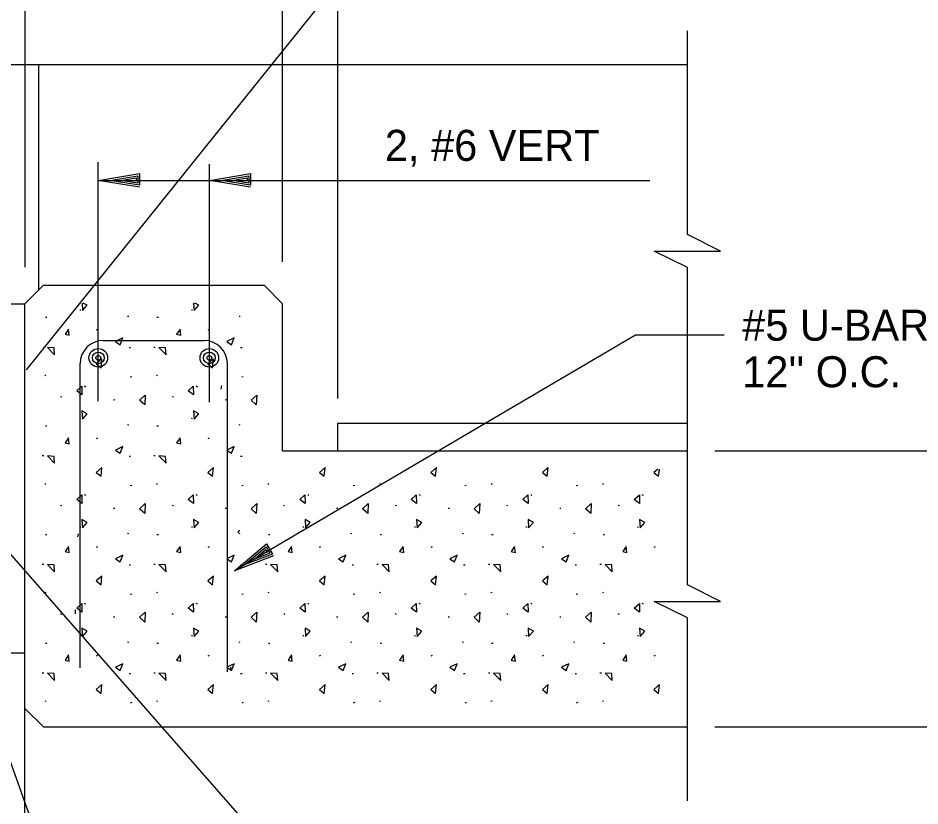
# Model space of a CAD drawing. Extents: x 22369.6 to 22428.3, y 22369.6 to 22415.
# Drawn here: x 22417.44 to 22422.89, y 22389.3 to 22394.06 of the extents above; entities that cross this region are included whole.
import ezdxf

# ---------------------------------------------------------------- set-up
doc = ezdxf.new("R2010")
doc.units = 0
for name, color, linetype in [('Level 1', 7, 'Continuous'), ('Level 10', 7, 'Continuous'), ('Level 2', 7, 'Continuous'), ('Level 4', 7, 'Continuous'), ('Level 7', 7, 'Continuous'), ('Level 8', 7, 'Continuous')]:
    doc.layers.add(name, color=color, linetype=linetype)

msp = doc.modelspace()

# ---------------------------------------------------------------- linework, layer by layer
at = {"layer": 'Level 1'}
for p, q in [((22417.4836, 22397.4896), (22417.4836, 22392.5564)), ((22419.0391, 22392.5884), (22419.0391, 22395.9148)), ((22419.3724, 22391.7634), (22419.3724, 22395.9228)), ((22417.4923, 22391.9355), (22420.152, 22395.2439)), ((22421.4835, 22392.7529), (22421.4835, 22393.9835)), ((22417.9264, 22391.7478), (22417.9264, 22393.1913)), ((22418.597, 22391.7409), (22418.597, 22393.1774)), ((22417.9264, 22393.0802), (22418.597, 22393.0802)), ((22417.9264, 22393.0802), (22417.9264, 22393.0802)), ((22418.0189, 22393.0802), (22418.0189, 22393.0802)), ((22418.597, 22393.0802), (22421.2567, 22393.0802)), ((22418.597, 22393.0802), (22418.597, 22393.0802)), ((22418.6894, 22393.0802), (22418.6894, 22393.0802)), ((22421.4835, 22390.6382), (22421.4835, 22392.5536)), ((22417.5502, 22392.0076), (22417.5502, 22392.0076)), ((22417.4923, 22391.9355), (22417.4923, 22391.9355)), ((22418.6691, 22391.8186), (22418.6726, 22391.8411)), ((22421.6488, 22391.4467), (22423.4552, 22391.4467)), ((22417.0669, 22391.1969), (22418.9221, 22389.0824)), ((22417.8033, 22390.9277), (22417.8065, 22390.9452)), ((22418.7704, 22390.9523), (22418.779, 22390.9706)), ((22418.8279, 22390.7697), (22418.8279, 22390.7697)), ((22418.7482, 22390.7228), (22418.7482, 22390.7228)), ((22417.789, 22390.4629), (22417.789, 22390.4863)), ((22421.4835, 22389.333), (22421.4835, 22390.4389)), ((22418.7288, 22390.1229), (22418.7273, 22390.1419)), ((22417.2233, 22390.0497), (22417.9908, 22387.8989)), ((22421.6488, 22389.7801), (22423.4552, 22389.7801))]:
    msp.add_line(p, q, dxfattribs=at)
for points in [[(22421.4835, 22392.5536), (22421.2835, 22392.6529), (22421.6831, 22392.6529), (22421.4835, 22392.7529)], [(22421.7045, 22392.1462), (22421.1698, 22392.1462), (22418.7482, 22390.7228)], [(22421.4835, 22390.4389), (22421.2835, 22390.5382), (22421.6831, 22390.5382), (22421.4835, 22390.6382)]]:
    msp.add_lwpolyline(points, dxfattribs=at)
at = {"layer": 'Level 10'}
for p, q in [((22417.4836, 22392.3356), (22417.5947, 22392.4467)), ((22417.5947, 22392.4467), (22418.928, 22392.4467)), ((22418.928, 22392.4467), (22419.0391, 22392.3356)), ((22417.4836, 22389.8912), (22417.4836, 22392.3356)), ((22419.0391, 22391.4467), (22419.0391, 22392.3356)), ((22417.9558, 22392.1133), (22418.5669, 22392.1133)), ((22417.8169, 22390.1365), (22417.8169, 22391.9744)), ((22418.7058, 22390.1131), (22418.7058, 22391.9744)), ((22419.0391, 22391.4467), (22421.4835, 22391.4467)), ((22417.4836, 22389.8912), (22417.5947, 22389.7801)), ((22417.5947, 22389.7801), (22421.4835, 22389.7801))]:
    msp.add_line(p, q, dxfattribs=at)
for centre, start, end in [((22417.9558, 22391.9744), 90, 180), ((22418.5669, 22391.9744), 0, 90)]:
    msp.add_arc(centre, 0.1389, start, end, dxfattribs=at)
at = {"layer": 'Level 2'}
for p, q in [((22419.3724, 22391.6133), (22421.4835, 22391.6133)), ((22419.3724, 22391.4467), (22419.3724, 22391.6133))]:
    msp.add_line(p, q, dxfattribs=at)
for points in [[(22418.1758, 22393.0389), (22417.9264, 22393.0802), (22418.1758, 22393.1215), (22418.1758, 22393.0509), (22417.9958, 22393.0802), (22418.1651, 22393.1082), (22418.1651, 22393.0629), (22418.0624, 22393.0802), (22418.1544, 22393.0949), (22418.1544, 22393.0762), (22418.1318, 22393.0802)], [(22418.8463, 22393.0389), (22418.597, 22393.0802), (22418.8463, 22393.1215), (22418.8463, 22393.0509), (22418.6663, 22393.0802), (22418.8357, 22393.1082), (22418.8357, 22393.0629), (22418.733, 22393.0802), (22418.825, 22393.0949), (22418.825, 22393.0762), (22418.8023, 22393.0802)], [(22418.9841, 22390.8135), (22418.7482, 22390.7228), (22418.9422, 22390.8848), (22418.978, 22390.8239), (22418.808, 22390.758), (22418.9398, 22390.8679), (22418.9627, 22390.8288), (22418.8655, 22390.7917), (22418.9373, 22390.851), (22418.9468, 22390.8349), (22418.9252, 22390.8269)]]:
    msp.add_lwpolyline(points, dxfattribs=at)
for centre, radius in [((22417.9265, 22392.0087), 0.0562), ((22417.9265, 22392.0087), 0.0352), ((22418.597, 22392.0087), 0.0562), ((22418.597, 22392.0087), 0.0352), ((22417.9265, 22392.0087), 0.0141), ((22418.597, 22392.0087), 0.0141)]:
    msp.add_circle(centre, radius, dxfattribs=at)
at = {"layer": 'Level 7'}
for p, q in [((22415.8447, 22393.78), (22421.4835, 22393.78)), ((22417.5669, 22392.4189), (22417.5669, 22393.78)), ((22417.4003, 22392.3356), (22417.4836, 22392.3356)), ((22417.4836, 22390.2245), (22417.4003, 22390.2245)), ((22417.4836, 22388.4468), (22417.4836, 22389.8912))]:
    msp.add_line(p, q, dxfattribs=at)
at = {"layer": 'Level 8'}
for p, q in [((22417.9264, 22393.0802), (22417.9264, 22393.0802)), ((22417.9958, 22393.0802), (22417.9958, 22393.0802)), ((22418.597, 22393.0802), (22418.597, 22393.0802)), ((22418.6663, 22393.0802), (22418.6663, 22393.0802)), ((22417.6165, 22392.2523), (22417.6075, 22392.2523)), ((22417.8216, 22392.2969), (22417.815, 22392.2974)), ((22418.1105, 22392.2579), (22418.1038, 22392.2591)), ((22418.2898, 22392.2523), (22418.2808, 22392.2523)), ((22418.495, 22392.2969), (22418.4883, 22392.2974)), ((22418.7838, 22392.2579), (22418.7771, 22392.2591)), ((22417.9218, 22392.1794), (22417.9138, 22392.1754)), ((22418.5951, 22392.1794), (22418.5871, 22392.1754)), ((22417.5971, 22392.0719), (22417.596, 22392.0719)), ((22418.1211, 22392.0688), (22418.1121, 22392.0688)), ((22418.2705, 22392.0719), (22418.262, 22392.0719)), ((22418.7945, 22392.0688), (22418.7855, 22392.0688)), ((22417.6103, 22391.9033), (22417.6038, 22391.9008)), ((22418.1283, 22391.8943), (22418.1193, 22391.8918)), ((22418.2836, 22391.9033), (22418.2771, 22391.9008)), ((22418.8016, 22391.8943), (22418.7926, 22391.8918)), ((22417.8516, 22391.8326), (22417.8441, 22391.8371)), ((22418.525, 22391.8326), (22418.5175, 22391.8371)), ((22417.7065, 22391.7706), (22417.6993, 22391.7739)), ((22418.3798, 22391.7706), (22418.3726, 22391.7739)), ((22418.0263, 22391.7546), (22418.019, 22391.7539)), ((22418.6996, 22391.7546), (22418.6923, 22391.7539)), ((22417.6165, 22391.5964), (22417.6075, 22391.5964)), ((22417.8216, 22391.6411), (22417.815, 22391.6416)), ((22418.1105, 22391.6021), (22418.1038, 22391.6033)), ((22418.2898, 22391.5964), (22418.2808, 22391.5964)), ((22418.495, 22391.6411), (22418.4883, 22391.6416)), ((22418.7838, 22391.6021), (22418.7771, 22391.6033)), ((22417.9218, 22391.5236), (22417.9138, 22391.5196)), ((22418.5951, 22391.5236), (22418.5871, 22391.5196)), ((22417.5971, 22391.4161), (22417.5886, 22391.4161)), ((22418.1211, 22391.4129), (22418.1121, 22391.4129)), ((22418.2705, 22391.4161), (22418.262, 22391.4161)), ((22418.7945, 22391.4129), (22418.7855, 22391.4129)), ((22417.6103, 22391.2474), (22417.6038, 22391.2449)), ((22418.1283, 22391.2384), (22418.1193, 22391.2359)), ((22418.2836, 22391.2474), (22418.2771, 22391.2449)), ((22418.8016, 22391.2384), (22418.7926, 22391.2359)), ((22418.957, 22391.2474), (22418.9505, 22391.2449)), ((22419.475, 22391.2384), (22419.466, 22391.2359)), ((22419.6303, 22391.2474), (22419.6238, 22391.2449)), ((22420.1483, 22391.2384), (22420.1393, 22391.2359)), ((22420.3036, 22391.2474), (22420.2971, 22391.2449)), ((22420.8216, 22391.2384), (22420.8126, 22391.2359)), ((22420.977, 22391.2474), (22420.9705, 22391.2449)), ((22417.8516, 22391.1768), (22417.8441, 22391.1813)), ((22418.525, 22391.1768), (22418.5175, 22391.1813)), ((22419.1983, 22391.1768), (22419.1908, 22391.1813)), ((22419.8716, 22391.1768), (22419.8641, 22391.1813)), ((22420.545, 22391.1768), (22420.5375, 22391.1813)), ((22421.2183, 22391.1768), (22421.2108, 22391.1813)), ((22417.7065, 22391.1148), (22417.6993, 22391.1181)), ((22418.3798, 22391.1148), (22418.3726, 22391.1181)), ((22419.0531, 22391.1148), (22419.046, 22391.1181)), ((22419.7265, 22391.1148), (22419.7193, 22391.1181)), ((22420.3998, 22391.1148), (22420.3926, 22391.1181)), ((22421.0731, 22391.1148), (22421.066, 22391.1181)), ((22418.0263, 22391.0988), (22418.019, 22391.0981)), ((22418.6996, 22391.0988), (22418.6923, 22391.0981)), ((22419.373, 22391.0988), (22419.3656, 22391.0981)), ((22420.0463, 22391.0988), (22420.039, 22391.0981)), ((22420.7196, 22391.0988), (22420.7123, 22391.0981)), ((22417.8216, 22390.9853), (22417.815, 22390.9858)), ((22418.1105, 22390.9463), (22418.1038, 22390.9474)), ((22418.495, 22390.9853), (22418.4883, 22390.9858)), ((22418.7838, 22390.9463), (22418.7771, 22390.9474)), ((22419.1683, 22390.9853), (22419.1616, 22390.9858)), ((22419.4571, 22390.9463), (22419.4505, 22390.9474)), ((22419.8416, 22390.9853), (22419.835, 22390.9858)), ((22420.1305, 22390.9463), (22420.1238, 22390.9474)), ((22420.515, 22390.9853), (22420.5083, 22390.9858)), ((22420.8038, 22390.9463), (22420.7971, 22390.9474)), ((22421.1883, 22390.9853), (22421.1816, 22390.9858)), ((22417.6165, 22390.9406), (22417.6075, 22390.9406)), ((22418.2898, 22390.9406), (22418.2808, 22390.9406)), ((22418.9631, 22390.9406), (22418.9541, 22390.9406)), ((22419.6365, 22390.9406), (22419.6275, 22390.9406)), ((22420.3098, 22390.9406), (22420.3008, 22390.9406)), ((22420.9831, 22390.9406), (22420.9741, 22390.9406)), ((22417.9218, 22390.8678), (22417.9138, 22390.8638)), ((22418.5951, 22390.8678), (22418.5871, 22390.8638)), ((22419.2685, 22390.8678), (22419.2605, 22390.8638)), ((22419.9418, 22390.8678), (22419.9338, 22390.8638)), ((22420.6151, 22390.8678), (22420.6071, 22390.8638)), ((22421.2885, 22390.8678), (22421.2805, 22390.8638)), ((22417.5971, 22390.7603), (22417.5886, 22390.7603)), ((22418.1211, 22390.7571), (22418.1121, 22390.7571)), ((22418.2705, 22390.7603), (22418.262, 22390.7603)), ((22418.7945, 22390.7571), (22418.7855, 22390.7571)), ((22418.808, 22390.758), (22418.808, 22390.758)), ((22418.9438, 22390.7603), (22418.9353, 22390.7603)), ((22419.4678, 22390.7571), (22419.4588, 22390.7571)), ((22419.6171, 22390.7603), (22419.6086, 22390.7603)), ((22420.1411, 22390.7571), (22420.1321, 22390.7571)), ((22420.2905, 22390.7603), (22420.282, 22390.7603)), ((22420.8145, 22390.7571), (22420.8055, 22390.7571)), ((22420.9638, 22390.7603), (22420.9553, 22390.7603)), ((22418.7482, 22390.7228), (22418.7482, 22390.7228)), ((22417.6103, 22390.5916), (22417.6038, 22390.5891)), ((22418.1283, 22390.5826), (22418.1193, 22390.5801)), ((22418.2836, 22390.5916), (22418.2771, 22390.5891)), ((22418.8016, 22390.5826), (22418.7926, 22390.5801)), ((22418.957, 22390.5916), (22418.9505, 22390.5891)), ((22419.475, 22390.5826), (22419.466, 22390.5801)), ((22419.6303, 22390.5916), (22419.6238, 22390.5891)), ((22420.1483, 22390.5826), (22420.1393, 22390.5801)), ((22420.3036, 22390.5916), (22420.2971, 22390.5891)), ((22420.8216, 22390.5826), (22420.8126, 22390.5801)), ((22420.977, 22390.5916), (22420.9705, 22390.5891)), ((22417.8516, 22390.5209), (22417.8441, 22390.5254)), ((22418.525, 22390.5209), (22418.5175, 22390.5254)), ((22419.1983, 22390.5209), (22419.1908, 22390.5254)), ((22419.8716, 22390.5209), (22419.8641, 22390.5254)), ((22420.545, 22390.5209), (22420.5375, 22390.5254)), ((22421.2183, 22390.5209), (22421.2108, 22390.5254)), ((22417.7065, 22390.4589), (22417.6993, 22390.4623)), ((22418.3798, 22390.4589), (22418.3726, 22390.4623)), ((22419.0531, 22390.4589), (22419.046, 22390.4623)), ((22419.7265, 22390.4589), (22419.7193, 22390.4623)), ((22420.3998, 22390.4589), (22420.3926, 22390.4623)), ((22421.0731, 22390.4589), (22421.066, 22390.4623)), ((22418.0263, 22390.4429), (22418.019, 22390.4423)), ((22418.6996, 22390.4429), (22418.6923, 22390.4423)), ((22419.373, 22390.4429), (22419.3656, 22390.4423)), ((22420.0463, 22390.4429), (22420.039, 22390.4423)), ((22420.7196, 22390.4429), (22420.7123, 22390.4423)), ((22417.8216, 22390.3294), (22417.815, 22390.3299)), ((22418.1105, 22390.2904), (22418.1038, 22390.2916)), ((22418.495, 22390.3294), (22418.4883, 22390.3299)), ((22418.7838, 22390.2904), (22418.7771, 22390.2916)), ((22419.1683, 22390.3294), (22419.1616, 22390.3299)), ((22419.4571, 22390.2904), (22419.4505, 22390.2916)), ((22419.8416, 22390.3294), (22419.835, 22390.3299)), ((22420.1305, 22390.2904), (22420.1238, 22390.2916)), ((22420.515, 22390.3294), (22420.5083, 22390.3299)), ((22420.8038, 22390.2904), (22420.7971, 22390.2916)), ((22421.1883, 22390.3294), (22421.1816, 22390.3299)), ((22417.6165, 22390.2848), (22417.6075, 22390.2848)), ((22418.2898, 22390.2848), (22418.2808, 22390.2848)), ((22418.9631, 22390.2848), (22418.9541, 22390.2848)), ((22419.6365, 22390.2848), (22419.6275, 22390.2848)), ((22420.3098, 22390.2848), (22420.3008, 22390.2848)), ((22420.9831, 22390.2848), (22420.9741, 22390.2848)), ((22417.9218, 22390.2119), (22417.9138, 22390.2079)), ((22418.5951, 22390.2119), (22418.5871, 22390.2079)), ((22419.2685, 22390.2119), (22419.2605, 22390.2079)), ((22419.9418, 22390.2119), (22419.9338, 22390.2079)), ((22420.6151, 22390.2119), (22420.6071, 22390.2079)), ((22421.2885, 22390.2119), (22421.2805, 22390.2079)), ((22417.5971, 22390.1044), (22417.5886, 22390.1044)), ((22418.1211, 22390.1013), (22418.1121, 22390.1013)), ((22418.2705, 22390.1044), (22418.262, 22390.1044)), ((22418.7945, 22390.1013), (22418.7855, 22390.1013)), ((22418.9438, 22390.1044), (22418.9353, 22390.1044)), ((22419.4678, 22390.1013), (22419.4588, 22390.1013)), ((22419.6171, 22390.1044), (22419.6086, 22390.1044)), ((22420.1411, 22390.1013), (22420.1321, 22390.1013)), ((22420.2905, 22390.1044), (22420.282, 22390.1044)), ((22420.8145, 22390.1013), (22420.8055, 22390.1013)), ((22420.9638, 22390.1044), (22420.9553, 22390.1044)), ((22417.6103, 22389.9358), (22417.6038, 22389.9333)), ((22418.1283, 22389.9268), (22418.1193, 22389.9243)), ((22418.2836, 22389.9358), (22418.2771, 22389.9333)), ((22418.8016, 22389.9268), (22418.7926, 22389.9243)), ((22418.957, 22389.9358), (22418.9505, 22389.9333)), ((22419.475, 22389.9268), (22419.466, 22389.9243)), ((22419.6303, 22389.9358), (22419.6238, 22389.9333)), ((22420.1483, 22389.9268), (22420.1393, 22389.9243)), ((22420.3036, 22389.9358), (22420.2971, 22389.9333)), ((22420.8216, 22389.9268), (22420.8126, 22389.9243)), ((22420.977, 22389.9358), (22420.9705, 22389.9333))]:
    msp.add_line(p, q, dxfattribs=at)
for points in [[(22417.8283, 22392.3392), (22417.8313, 22392.2946), (22417.8598, 22392.3266), (22417.8361, 22392.3392)], [(22418.5016, 22392.3392), (22418.5046, 22392.2946), (22418.5331, 22392.3266), (22418.5095, 22392.3392)], [(22420.6406, 22391.3456), (22420.608, 22391.3171), (22420.6363, 22391.2933), (22420.642, 22391.3456)], [(22421.3047, 22391.3375), (22421.2813, 22391.3171), (22421.3096, 22391.2933), (22421.3144, 22391.3374)]]:
    msp.add_lwpolyline(points, dxfattribs=at)
for points in [[(22417.7511, 22392.1456), (22417.7465, 22392.1821), (22417.726, 22392.1516)], [(22418.4245, 22392.1456), (22418.4198, 22392.1821), (22418.3993, 22392.1516)], [(22418.0581, 22392.0883), (22418.074, 22392.1291), (22418.0298, 22392.1076)], [(22418.7315, 22392.0883), (22418.7473, 22392.1291), (22418.7031, 22392.1076)], [(22417.6596, 22392.0698), (22417.6196, 22392.0719), (22417.663, 22392.0276)], [(22418.333, 22392.0698), (22418.293, 22392.0719), (22418.3363, 22392.0276)], [(22417.9488, 22392.0028), (22417.9146, 22391.9729), (22417.943, 22391.9491)], [(22418.6221, 22392.0028), (22418.588, 22391.9729), (22418.6163, 22391.9491)], [(22417.828, 22391.7854), (22417.796, 22391.8096), (22417.8266, 22391.8368)], [(22418.5013, 22391.7854), (22418.4693, 22391.8096), (22418.5, 22391.8368)], [(22418.2065, 22391.7253), (22418.1756, 22391.7538), (22418.2098, 22391.7843)], [(22418.8798, 22391.7253), (22418.849, 22391.7538), (22418.8831, 22391.7843)], [(22417.8313, 22391.6388), (22417.8598, 22391.6708), (22417.828, 22391.6878)], [(22418.5046, 22391.6388), (22418.5331, 22391.6708), (22418.5013, 22391.6878)], [(22417.7511, 22391.4898), (22417.7465, 22391.5263), (22417.726, 22391.4958)], [(22418.4245, 22391.4898), (22418.4198, 22391.5263), (22418.3993, 22391.4958)], [(22418.0581, 22391.4324), (22418.074, 22391.4733), (22418.0298, 22391.4518)], [(22418.7315, 22391.4324), (22418.7473, 22391.4733), (22418.7031, 22391.4518)], [(22417.6596, 22391.4139), (22417.6196, 22391.4161), (22417.663, 22391.3718)], [(22418.333, 22391.4139), (22418.293, 22391.4161), (22418.3363, 22391.3718)], [(22417.9488, 22391.3469), (22417.9146, 22391.3171), (22417.943, 22391.2933)], [(22418.6221, 22391.3469), (22418.588, 22391.3171), (22418.6163, 22391.2933)], [(22419.2955, 22391.3469), (22419.2613, 22391.3171), (22419.2896, 22391.2933)], [(22419.9688, 22391.3469), (22419.9346, 22391.3171), (22419.963, 22391.2933)], [(22417.828, 22391.1296), (22417.796, 22391.1538), (22417.8266, 22391.1809)], [(22418.5013, 22391.1296), (22418.4693, 22391.1538), (22418.5, 22391.1809)], [(22419.1746, 22391.1296), (22419.1426, 22391.1538), (22419.1733, 22391.1809)], [(22419.848, 22391.1296), (22419.816, 22391.1538), (22419.8466, 22391.1809)], [(22420.5213, 22391.1296), (22420.4893, 22391.1538), (22420.52, 22391.1809)], [(22421.1946, 22391.1296), (22421.1626, 22391.1538), (22421.1933, 22391.1809)], [(22418.2065, 22391.0694), (22418.1756, 22391.0979), (22418.2098, 22391.1284)], [(22418.8798, 22391.0694), (22418.849, 22391.0979), (22418.8831, 22391.1284)], [(22419.5531, 22391.0694), (22419.5223, 22391.0979), (22419.5565, 22391.1284)], [(22420.2265, 22391.0694), (22420.1956, 22391.0979), (22420.2298, 22391.1284)], [(22420.8998, 22391.0694), (22420.869, 22391.0979), (22420.9031, 22391.1284)], [(22417.8313, 22390.9829), (22417.8598, 22391.0149), (22417.828, 22391.0319)], [(22418.5046, 22390.9829), (22418.5331, 22391.0149), (22418.5013, 22391.0319)], [(22419.178, 22390.9829), (22419.2065, 22391.0149), (22419.1746, 22391.0319)], [(22419.8513, 22390.9829), (22419.8798, 22391.0149), (22419.848, 22391.0319)], [(22420.5246, 22390.9829), (22420.5531, 22391.0149), (22420.5213, 22391.0319)], [(22421.198, 22390.9829), (22421.2265, 22391.0149), (22421.1946, 22391.0319)], [(22417.7511, 22390.8339), (22417.7465, 22390.8704), (22417.726, 22390.8399)], [(22418.4245, 22390.8339), (22418.4198, 22390.8704), (22418.3993, 22390.8399)], [(22419.0978, 22390.8339), (22419.0931, 22390.8704), (22419.0726, 22390.8399)], [(22419.7711, 22390.8339), (22419.7665, 22390.8704), (22419.746, 22390.8399)], [(22420.4445, 22390.8339), (22420.4398, 22390.8704), (22420.4193, 22390.8399)], [(22421.1178, 22390.8339), (22421.1131, 22390.8704), (22421.0926, 22390.8399)], [(22418.0581, 22390.7766), (22418.074, 22390.8174), (22418.0298, 22390.7959)], [(22418.7315, 22390.7766), (22418.7473, 22390.8174), (22418.7031, 22390.7959)], [(22419.4048, 22390.7766), (22419.4206, 22390.8174), (22419.3765, 22390.7959)], [(22420.0781, 22390.7766), (22420.094, 22390.8174), (22420.0498, 22390.7959)], [(22420.7515, 22390.7766), (22420.7673, 22390.8174), (22420.7231, 22390.7959)], [(22417.6596, 22390.7581), (22417.6196, 22390.7603), (22417.663, 22390.7159)], [(22418.333, 22390.7581), (22418.293, 22390.7603), (22418.3363, 22390.7159)], [(22419.0063, 22390.7581), (22418.9663, 22390.7603), (22419.0096, 22390.7159)], [(22419.6796, 22390.7581), (22419.6396, 22390.7603), (22419.683, 22390.7159)], [(22420.353, 22390.7581), (22420.313, 22390.7603), (22420.3563, 22390.7159)], [(22421.0263, 22390.7581), (22420.9863, 22390.7603), (22421.0296, 22390.7159)], [(22417.9488, 22390.6911), (22417.9146, 22390.6613), (22417.943, 22390.6374)], [(22418.6221, 22390.6911), (22418.588, 22390.6613), (22418.6163, 22390.6374)], [(22419.2955, 22390.6911), (22419.2613, 22390.6613), (22419.2896, 22390.6374)], [(22419.9688, 22390.6911), (22419.9346, 22390.6613), (22419.963, 22390.6374)], [(22420.6421, 22390.6911), (22420.608, 22390.6613), (22420.6363, 22390.6374)], [(22417.828, 22390.4738), (22417.796, 22390.4979), (22417.8266, 22390.5251)], [(22418.5013, 22390.4738), (22418.4693, 22390.4979), (22418.5, 22390.5251)], [(22419.1746, 22390.4738), (22419.1426, 22390.4979), (22419.1733, 22390.5251)], [(22419.848, 22390.4738), (22419.816, 22390.4979), (22419.8466, 22390.5251)], [(22420.5213, 22390.4738), (22420.4893, 22390.4979), (22420.52, 22390.5251)], [(22421.1946, 22390.4738), (22421.1626, 22390.4979), (22421.1933, 22390.5251)], [(22418.2065, 22390.4136), (22418.1756, 22390.4421), (22418.2098, 22390.4726)], [(22418.8798, 22390.4136), (22418.849, 22390.4421), (22418.8831, 22390.4726)], [(22419.5531, 22390.4136), (22419.5223, 22390.4421), (22419.5565, 22390.4726)], [(22420.2265, 22390.4136), (22420.1956, 22390.4421), (22420.2298, 22390.4726)], [(22420.8998, 22390.4136), (22420.869, 22390.4421), (22420.9031, 22390.4726)], [(22417.8313, 22390.3271), (22417.8598, 22390.3591), (22417.828, 22390.3761)], [(22418.5046, 22390.3271), (22418.5331, 22390.3591), (22418.5013, 22390.3761)], [(22419.178, 22390.3271), (22419.2065, 22390.3591), (22419.1746, 22390.3761)], [(22419.8513, 22390.3271), (22419.8798, 22390.3591), (22419.848, 22390.3761)], [(22420.5246, 22390.3271), (22420.5531, 22390.3591), (22420.5213, 22390.3761)], [(22421.198, 22390.3271), (22421.2265, 22390.3591), (22421.1946, 22390.3761)], [(22417.7511, 22390.1781), (22417.7465, 22390.2146), (22417.726, 22390.1841)], [(22418.4245, 22390.1781), (22418.4198, 22390.2146), (22418.3993, 22390.1841)], [(22419.0978, 22390.1781), (22419.0931, 22390.2146), (22419.0726, 22390.1841)], [(22419.7711, 22390.1781), (22419.7665, 22390.2146), (22419.746, 22390.1841)], [(22420.4445, 22390.1781), (22420.4398, 22390.2146), (22420.4193, 22390.1841)], [(22421.1178, 22390.1781), (22421.1131, 22390.2146), (22421.0926, 22390.1841)], [(22418.0581, 22390.1208), (22418.074, 22390.1616), (22418.0298, 22390.1401)], [(22418.7315, 22390.1208), (22418.7473, 22390.1616), (22418.7031, 22390.1401)], [(22419.4048, 22390.1208), (22419.4206, 22390.1616), (22419.3765, 22390.1401)], [(22420.0781, 22390.1208), (22420.094, 22390.1616), (22420.0498, 22390.1401)], [(22420.7515, 22390.1208), (22420.7673, 22390.1616), (22420.7231, 22390.1401)], [(22417.6596, 22390.1023), (22417.6196, 22390.1044), (22417.663, 22390.0601)], [(22418.333, 22390.1023), (22418.293, 22390.1044), (22418.3363, 22390.0601)], [(22419.0063, 22390.1023), (22418.9663, 22390.1044), (22419.0096, 22390.0601)], [(22419.6796, 22390.1023), (22419.6396, 22390.1044), (22419.683, 22390.0601)], [(22420.353, 22390.1023), (22420.313, 22390.1044), (22420.3563, 22390.0601)], [(22421.0263, 22390.1023), (22420.9863, 22390.1044), (22421.0296, 22390.0601)], [(22417.9488, 22390.0353), (22417.9146, 22390.0054), (22417.943, 22389.9816)], [(22418.6221, 22390.0353), (22418.588, 22390.0054), (22418.6163, 22389.9816)], [(22419.2955, 22390.0353), (22419.2613, 22390.0054), (22419.2896, 22389.9816)], [(22419.9688, 22390.0353), (22419.9346, 22390.0054), (22419.963, 22389.9816)], [(22420.6421, 22390.0353), (22420.608, 22390.0054), (22420.6363, 22389.9816)], [(22421.3155, 22390.0353), (22421.2813, 22390.0054), (22421.3096, 22389.9816)]]:
    msp.add_lwpolyline(points, close=True, dxfattribs=at)

# ---------------------------------------------------------------- texts
at = {"layer": 'Level 4'}
for s, p in [('2, #6 VERT', (22419.6568, 22393.198)), ('#5 U-BARS,', (22421.8143, 22392.1121)), ("12'' O.C.", (22421.8143, 22391.8309))]:
    msp.add_text(s, height=0.1875, dxfattribs=at).set_placement(p)

doc.saveas('drawing.dxf')
